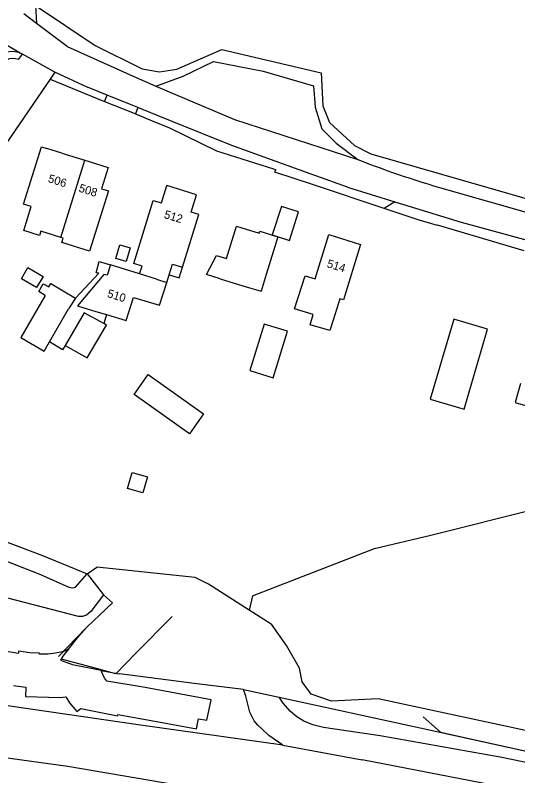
# Model space of a CAD drawing. Extents: x 194485 to 197793, y 468269 to 470822.
# Drawn here: x 196049.6 to 196122.3, y 469112.8 to 469222.9 of the extents above; entities that cross this region are included whole.
import ezdxf

# ---------------------------------------------------------------- set-up
doc = ezdxf.new("R2010")
doc.units = 0
for name, color, linetype in [('BGT begrenzing kruinlijn', 7, 'Continuous'), ('BGT grensvlak begroeid terreindeel', 7, 'Continuous'), ('BGT grensvlak begroeid terreindeel LR', 7, 'Continuous'), ('BGT grensvlak gebouwinstallatie plus 1', 7, 'Continuous'), ('BGT grensvlak onbegroeid terreindeel', 7, 'Continuous'), ('BGT grensvlak ondersteunend wegdeel', 7, 'Continuous'), ('BGT grensvlak overig bouwwerk uitbreiding populatie', 7, 'Continuous'), ('BGT grensvlak pand op maaiveld', 7, 'Continuous'), ('BGT grensvlak pand op maaiveld LR', 7, 'Continuous'), ('BGT grensvlak wegdeel', 7, 'Continuous'), ('BGT lijnelement scheiding hek', 7, 'Continuous'), ('BGT tekst huisnummerreeks', 7, 'Continuous')]:
    doc.layers.add(name, color=color, linetype=linetype)

msp = doc.modelspace()

# ---------------------------------------------------------------- linework, layer by layer
at = {"layer": 'BGT begrenzing kruinlijn'}
for p, q in [((196058.8, 469135.89), (196037.29, 469141.47)), ((196062.42, 469139.04), (196060.56, 469136.61)), ((196059.94, 469136.1), (196059.39, 469135.88)), ((196060.56, 469136.61), (196059.94, 469136.1)), ((196059.39, 469135.88), (196058.8, 469135.89)), ((196083, 469124.37), (196082.66, 469125.31)), ((196083.55, 469122.03), (196083, 469124.37)), ((196084.21, 469120.79), (196083.55, 469122.03)), ((196084.71, 469120.16), (196084.21, 469120.79)), ((196085.29, 469119.62), (196084.71, 469120.16)), ((196086.3, 469118.67), (196085.29, 469119.62)), ((196088.32, 469117.26), (196086.3, 469118.67)), ((196088.32, 469117.26), (196099.82, 469115.15)), ((196125.51, 469110.16), (196099.82, 469115.15))]:
    msp.add_line(p, q, dxfattribs=at)
at = {"layer": 'BGT grensvlak begroeid terreindeel'}
for p, q in [((196060.06, 469142.05), (196062.42, 469139.04)), ((196062.42, 469139.04), (196063.72, 469137.84)), ((196057.36, 469131.15), (196058.83, 469133.02)), ((196082.66, 469125.31), (196087.8, 469124.2))]:
    msp.add_line(p, q, dxfattribs=at)
for points in [[(196063.72, 469137.84), (196059.98, 469134.33), (196058.83, 469133.02)], [(196086.69, 469134.76), (196086.67, 469134.79), (196083.48, 469136.82)], [(196151.92, 469113.25), (196102.11, 469123.98), (196095.38, 469123.62), (196092.44, 469124.65), (196091.14, 469126.41), (196090.73, 469128.4), (196088.86, 469131.67), (196086.69, 469134.76)], [(196062.09, 469128.07), (196064.37, 469127.62), (196064.71, 469127.58)], [(196082.66, 469125.31), (196075.9, 469126.16), (196064.71, 469127.58)], [(196434.71, 469015.8), (196400.08, 469030.84), (196373.46, 469042.14), (196354.81, 469049.48), (196329.14, 469058.95), (196305.82, 469067.12), (196287.13, 469073.34), (196263.31, 469080.74), (196240.21, 469087.53), (196215.65, 469094.21), (196189.11, 469100.65), (196136.13, 469112.17), (196119.75, 469115.54), (196102.39, 469118.61), (196094.23, 469119.82), (196092.68, 469120.22), (196091.38, 469120.74), (196090.36, 469121.37), (196089.46, 469122.16), (196088.39, 469123.35), (196087.8, 469124.2)], [(196087.8, 469124.2), (196108.2, 469119.79), (196126.38, 469115.77), (196143.27, 469112.16), (196176.14, 469104.87), (196198.98, 469099.42), (196217.13, 469094.83), (196250.76, 469085.84), (196271.73, 469079.61), (196286.17, 469075.15), (196311.17, 469066.15), (196337.58, 469056.94), (196358.91, 469049.17), (196382.64, 469039.43), (196437.42, 469015.79), (196455.06, 469007.97), (196467.57, 469002.33)]]:
    msp.add_lwpolyline(points, dxfattribs=at)
at = {"layer": 'BGT grensvlak begroeid terreindeel LR'}
msp.add_lwpolyline([(196036.85, 469147.53), (196043.36, 469145.61), (196047.9, 469144.08), (196053.3, 469141.96), (196057.4, 469140.11), (196057.99, 469140.01), (196058.36, 469140.14), (196060.06, 469142.05)], dxfattribs=at)
at = {"layer": 'BGT grensvlak gebouwinstallatie plus 1'}
for p, q in [((196061.34, 469185.63), (196061.79, 469187.27)), ((196061.79, 469187.27), (196063.4, 469186.77)), ((196058.37, 469181.96), (196061.75, 469185.54)), ((196061.75, 469185.54), (196061.34, 469185.63)), ((196073.33, 469184.89), (196073.82, 469186.42)), ((196071.9, 469185.34), (196073.33, 469184.89)), ((196062.83, 469179.57), (196062.46, 469178.26)), ((196056.5, 469174.49), (196054.59, 469175.62)), ((196056.85, 469175.1), (196056.5, 469174.49))]:
    msp.add_line(p, q, dxfattribs=at)
msp.add_lwpolyline([(196122.71, 469169.62), (196121.91, 469166.86), (196133.44, 469163.5), (196134.24, 469166.26)], dxfattribs=at)
at = {"layer": 'BGT grensvlak onbegroeid terreindeel'}
for p, q in [((196054.69, 469213.65), (196014.79, 469155.37)), ((196054.69, 469213.65), (196059.63, 469211.63)), ((196059.63, 469211.63), (196062.57, 469210.42)), ((196067.01, 469208.61), (196069.7, 469207.51)), ((196069.7, 469207.51), (196071.95, 469206.59)), ((196071.95, 469206.59), (196078.72, 469203.26)), ((196078.72, 469203.26), (196086.98, 469200.67)), ((196086.98, 469200.67), (196087.32, 469200.57)), ((196087.2, 469200.2), (196087.32, 469200.57)), ((196092.6, 469198.39), (196087.2, 469200.2)), ((196103, 469194.9), (196092.6, 469198.39)), ((196109.73, 469147.66), (196129.68, 469152.66)), ((196101.57, 469145.73), (196109.73, 469147.66)), ((196083.93, 469138.88), (196101.57, 469145.73)), ((196060.06, 469142.05), (196061.45, 469143)), ((196075.66, 469141.51), (196061.45, 469143)), ((196083.93, 469138.88), (196083.48, 469136.82)), ((196057.36, 469131.15), (196056.55, 469130.12))]:
    msp.add_line(p, q, dxfattribs=at)
for points in [[(196110.69, 469192.46), (196107.89, 469193.26), (196103, 469194.9)], [(196123.22, 469188.79), (196110.7, 469192.49), (196110.69, 469192.46)], [(196033.67, 469151.38), (196038.47, 469150.05), (196041.43, 469149.31), (196053.58, 469144.73), (196060.06, 469142.05)], [(196083.48, 469136.82), (196077.59, 469140.55), (196075.67, 469141.55), (196075.66, 469141.51)], [(196057.36, 469131.15), (196056.85, 469130.88), (196056.24, 469130.73), (196055.49, 469130.6), (196054.42, 469130.42), (196054.38, 469130.45), (196053.16, 469130.43), (196053.16, 469130.56), (196051.76, 469130.63), (196050.17, 469130.88), (196050.05, 469130.52), (196046.97, 469131.08)], [(196056.55, 469130.12), (196056.18, 469129.57), (196057.48, 469129.07)], [(196062.09, 469128.07), (196057.93, 469128.89), (196057.48, 469129.07)], [(196049.39, 469125.9), (196051.17, 469125.68), (196051.11, 469124.29), (196056.08, 469124.17), (196056.96, 469124.26), (196057.49, 469123.38), (196058.53, 469122.12), (196059.12, 469122.58), (196064.43, 469121.52), (196064.46, 469121.68), (196069.81, 469120.76), (196075.85, 469119.63), (196076.15, 469121.09), (196077.34, 469120.87), (196077.99, 469123.84), (196068.43, 469125.59), (196062.87, 469126.52), (196062.59, 469126.89), (196062.4, 469127.23), (196062.09, 469128.07)]]:
    msp.add_lwpolyline(points, dxfattribs=at)
at = {"layer": 'BGT grensvlak ondersteunend wegdeel'}
for p, q in [((196055.38, 469214.65), (196054.69, 469213.65)), ((196104.55, 469195.87), (196103, 469194.9))]:
    msp.add_line(p, q, dxfattribs=at)
msp.add_lwpolyline([(196052.58, 469224.29), (196061.22, 469218.5), (196068, 469215.13), (196070.5, 469214.69), (196073, 469215.06), (196079.5, 469217.92), (196093.86, 469214.54), (196094.12, 469209.76), (196095.08, 469207.35), (196098.7, 469204.04), (196101.07, 469202.85), (196141.58, 469191.14)], dxfattribs=at)
at = {"layer": 'BGT grensvlak overig bouwwerk uitbreiding populatie'}
for p, q in [((196064.17, 469187.69), (196064.75, 469189.68)), ((196064.75, 469189.68), (196066.24, 469189.25)), ((196066.24, 469189.25), (196065.67, 469187.26)), ((196065.67, 469187.26), (196064.17, 469187.69)), ((196050.54, 469184.74), (196051.48, 469186.36)), ((196051.48, 469186.36), (196053.66, 469185.1)), ((196052.71, 469183.48), (196050.54, 469184.74)), ((196053.66, 469185.1), (196052.71, 469183.48)), ((196065.86, 469154.42), (196066.53, 469156.74)), ((196066.53, 469156.74), (196068.76, 469156.09)), ((196068.76, 469156.09), (196068.09, 469153.78)), ((196068.09, 469153.78), (196065.86, 469154.42))]:
    msp.add_line(p, q, dxfattribs=at)
msp.add_lwpolyline([(196088.12, 469195.23), (196086.8, 469191.11), (196089.29, 469190.31), (196090.62, 469194.42), (196088.12, 469195.23)], dxfattribs=at)
at = {"layer": 'BGT grensvlak pand op maaiveld'}
for p, q in [((196056.38, 469202.93), (196054.2, 469203.61)), ((196056.38, 469202.93), (196059.73, 469201.89)), ((196056.24, 469190.71), (196053.34, 469191.66)), ((196056.56, 469190.61), (196056.24, 469190.71)), ((196063.4, 469186.77), (196062.93, 469185.26)), ((196067.63, 469185.45), (196063.4, 469186.77)), ((196071.56, 469184.23), (196071.9, 469185.34)), ((196079.26, 469184.73), (196082.54, 469183.72)), ((196082.54, 469183.72), (196085.18, 469182.94)), ((196058.37, 469181.96), (196057.35, 469180.4)), ((196054.59, 469175.62), (196057.35, 469180.4)), ((196061.32, 469180.02), (196062.83, 469179.57)), ((196083.56, 469171.46), (196086.93, 469170.41))]:
    msp.add_line(p, q, dxfattribs=at)
for points in [[(196051.95, 469195.19), (196050.85, 469195.54), (196053.44, 469203.85), (196054.2, 469203.61)], [(196059.73, 469201.89), (196063.08, 469200.84), (196062.13, 469197.77), (196063.15, 469197.47), (196060.39, 469188.74), (196056.37, 469190.02), (196056.56, 469190.61)], [(196067.63, 469185.45), (196067.98, 469186.58), (196066.8, 469186.94), (196069.61, 469196.09), (196070.78, 469195.72), (196071.55, 469198.23)], [(196073.82, 469186.42), (196076.21, 469194.06), (196075.07, 469194.41), (196075.87, 469196.9), (196071.55, 469198.23)], [(196053.34, 469191.66), (196053.14, 469191.03), (196050.88, 469191.73), (196051.95, 469195.19)], [(196080.18, 469187.7), (196081.62, 469192.37), (196084.91, 469191.36), (196084.99, 469191.63), (196087.63, 469190.8), (196085.93, 469185.36), (196085.18, 469182.94)], [(196092.72, 469179.59), (196090.02, 469180.38), (196091.55, 469185.19), (196093.02, 469184.73), (196094.99, 469191.15)], [(196094.99, 469191.15), (196099.58, 469189.72), (196097.12, 469181.72)], [(196079.26, 469184.73), (196077.3, 469185.36), (196078.75, 469188.1), (196080.18, 469187.7)], [(196071.9, 469185.34), (196072.38, 469186.88), (196073.82, 469186.42)], [(196062.93, 469185.26), (196062.45, 469185.39), (196058.64, 469180.83), (196061.32, 469180.02)], [(196053.98, 469182.35), (196053.06, 469182.9), (196053.69, 469184.04), (196054.48, 469183.57), (196054.79, 469184.07), (196058.37, 469181.96)], [(196062.83, 469179.57), (196065.68, 469178.7), (196066.73, 469182.06), (196070.52, 469180.91), (196071.56, 469184.23)], [(196053.98, 469182.35), (196050.44, 469176.24), (196053.82, 469174.29), (196054.59, 469175.62)], [(196097.12, 469181.72), (196096.57, 469181.84), (196095.6, 469178.74)], [(196062.46, 469178.26), (196059.63, 469179.84), (196056.85, 469175.1)], [(196095.6, 469178.74), (196095.14, 469177.28), (196092.29, 469178.11), (196092.72, 469179.59)], [(196114.53, 469165.89), (196117.93, 469177.48), (196113.05, 469178.92), (196109.65, 469167.32), (196114.53, 469165.89)], [(196056.85, 469175.1), (196060.03, 469173.33), (196062.82, 469178.06), (196062.46, 469178.26)], [(196086.93, 469170.41), (196089, 469177.15), (196085.63, 469178.19), (196083.56, 469171.46)], [(196068.88, 469170.89), (196076.87, 469165.21), (196074.82, 469162.32), (196066.83, 469168), (196068.88, 469170.89)]]:
    msp.add_lwpolyline(points, dxfattribs=at)
at = {"layer": 'BGT grensvlak pand op maaiveld LR'}
for p, q in [((196056.24, 469190.71), (196059.73, 469201.89)), ((196070.09, 469184.69), (196067.63, 469185.45)), ((196070.09, 469184.69), (196071.56, 469184.23))]:
    msp.add_line(p, q, dxfattribs=at)
at = {"layer": 'BGT grensvlak wegdeel'}
for p, q in [((196052.58, 469224.29), (196052.71, 469221.7)), ((196052.71, 469221.7), (196050.88, 469223.07)), ((196057.16, 469218.37), (196052.71, 469221.7)), ((196045.29, 469220.39), (196050.68, 469217.27)), ((196057.16, 469218.37), (196066.71, 469214.07)), ((196050.12, 469216.49), (196050.68, 469217.27)), ((196055.38, 469214.65), (196050.68, 469217.27)), ((196060.13, 469212.45), (196055.38, 469214.65)), ((196066.71, 469214.07), (196069.96, 469212.6)), ((196069.96, 469212.6), (196081.33, 469207.79)), ((196062.57, 469210.42), (196062.93, 469211.3)), ((196067.37, 469209.51), (196062.93, 469211.3)), ((196062.57, 469210.42), (196066.58, 469208.79)), ((196066.58, 469208.79), (196067.01, 469208.61)), ((196067.37, 469209.51), (196067.01, 469208.61)), ((196070.05, 469208.42), (196067.37, 469209.51)), ((196072.33, 469207.5), (196070.05, 469208.42)), ((196081.33, 469207.79), (196099.2, 469201.99)), ((196092.44, 469199.88), (196087.24, 469201.75)), ((196093.79, 469199.39), (196092.44, 469199.88)), ((196097.69, 469197.99), (196093.79, 469199.39)), ((196097.69, 469197.99), (196104.55, 469195.87)), ((196131.11, 469192.19), (196112.7, 469197.45)), ((196104.55, 469195.87), (196114.12, 469192.92)), ((196114.12, 469192.92), (196123.65, 469190.35))]:
    msp.add_line(p, q, dxfattribs=at)
for points in [[(196069.96, 469212.6), (196073.91, 469214.05), (196078.3, 469216.18), (196085.5, 469214.79), (196092.79, 469212.67), (196093.03, 469209.57), (196093.95, 469206.43), (196096.05, 469204.37), (196099.2, 469201.99)], [(196062.93, 469211.3), (196060.31, 469212.36), (196060.13, 469212.45)], [(196087.24, 469201.75), (196080.94, 469204.02), (196072.33, 469207.5)], [(196088.32, 469117.26), (196067.43, 469120.21), (196049.2, 469122.88), (196034.4, 469125.24), (196017.38, 469127.61), (195999.89, 469129.59)], [(195999.02, 469122.04), (196029.6, 469118.02), (196057.23, 469114.23), (196080.95, 469110.16), (196100.51, 469106.11), (196139.05, 469098.88), (196174.84, 469090.53), (196207.41, 469082.21), (196234.02, 469074.82), (196264.51, 469065.6), (196275.61, 469062.12), (196277.85, 469061.15), (196295.25, 469055.54), (196322.11, 469046.36), (196335.98, 469041.34), (196360.04, 469032.16), (196376.51, 469025.67), (196401.49, 469015.41), (196430.94, 469002.41)]]:
    msp.add_lwpolyline(points, dxfattribs=at)
for centre, radius, start, end in [((196049.26, 469214.58), 3.04, 62.1732, 146.2269), ((196049.32, 469214.11), 2.51, 71.3631, 150.8553), ((196155, 469345.55), 154.02, 248.7594, 254.0576)]:
    msp.add_arc(centre, radius, start, end, dxfattribs=at)
at = {"layer": 'BGT lijnelement scheiding hek'}
for p, q in [((196055.9, 469130.09), (196059.85, 469134.2)), ((196108.62, 469121.35), (196111.13, 469119.14))]:
    msp.add_line(p, q, dxfattribs=at)
for points in [[(196033.67, 469151.38), (196041.43, 469149.31), (196053.58, 469144.73), (196060.06, 469142.05)], [(196064.2, 469127.58), (196067.13, 469130.62), (196072.31, 469135.89)], [(196064.2, 469127.58), (196060.66, 469128.55), (196056.46, 469129.67)], [(196111.13, 469119.14), (196126.38, 469115.77), (196143.27, 469112.16), (196176.14, 469104.87), (196198.98, 469099.42), (196217.13, 469094.83), (196250.76, 469085.84), (196271.73, 469079.61), (196286.17, 469075.15), (196311.17, 469066.15), (196337.58, 469056.94), (196358.91, 469049.17), (196382.64, 469039.43), (196437.42, 469015.79)]]:
    msp.add_lwpolyline(points, dxfattribs=at)

# ---------------------------------------------------------------- texts
at = {"layer": 'BGT tekst huisnummerreeks'}
for s, rotation, p in [('506', 342.7, (196054.3, 469198.76)), ('508', 342.7, (196058.74, 469197.38)), ('512', 343, (196071.07, 469193.56)), ('514', 342.7, (196094.62, 469186.45)), ('510', 342.7, (196062.85, 469182.13))]:
    msp.add_text(s, height=1.2, rotation=rotation, dxfattribs=at).set_placement(p)

doc.saveas('drawing.dxf')
